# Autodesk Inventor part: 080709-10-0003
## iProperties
Created: 2008-07
Part Number: 080709-10-0003
Document SubType Name: Modeling
Designer: mp
Density: 1 g/cm^3
Stock Number: 080709-10-0003
Author: mp
